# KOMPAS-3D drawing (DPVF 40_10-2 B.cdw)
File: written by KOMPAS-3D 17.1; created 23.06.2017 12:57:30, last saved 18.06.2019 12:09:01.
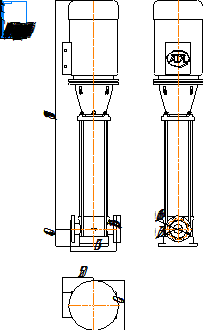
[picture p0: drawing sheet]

Sheet 1: A4, portrait

Title block, sheet 1: name: DPVF 40_10-2 B; material: Внимание! Данный продукт является объектом авторского права ООО «Торговый Дом АДЛ». / Запрещается изменение, копирование, распространение / (в том числе путем копирования на другие сайты и ресурсы в Интернете) / или любое иное использование информации и объектов без предварительного / согласия правообладателя (ООО «Торговый Дом АДЛ»).; scale: 1:1; sheets: 1; organisation: ООО "Торговый дом АДЛ"; sheet format: A4; stored path: C:\Клочков АВ\Насосы\DP PAMS\DPVF 40\Компас 2d\DPVF 40_10-2 B.cdw

Views: Спереди 1
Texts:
  Клочков АВ
  ООО АДЛ ГРУПП
Dimensions and other numbers on the sheet: 365; 250; 400; 209,6; 1819,5; 140; 168,1; 76,2; 1:1; 1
